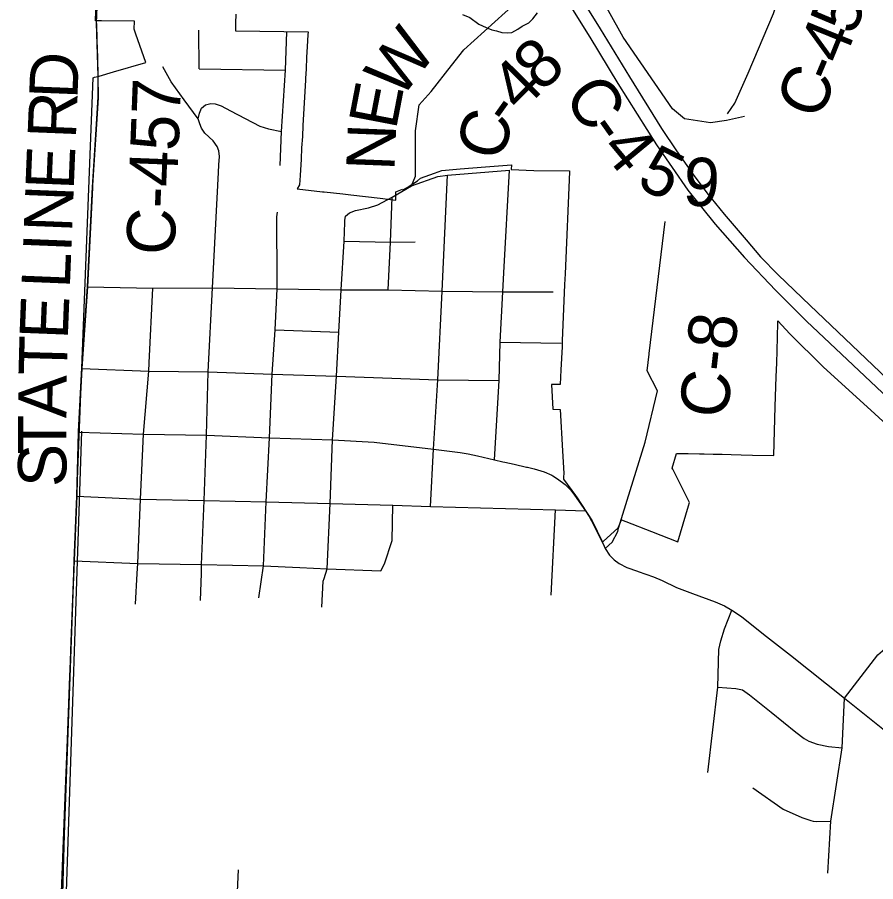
# Model space of a CAD drawing. Extents: x -7.5 to 26.5, y 3.5 to 25.5.
# Drawn here: x -5.276 to -4.268, y 21.705 to 22.72 of the extents above; entities that cross this region are included whole.
import ezdxf

# ---------------------------------------------------------------- set-up
doc = ezdxf.new("R2010")
doc.units = 0
for name, color, linetype in [('GM_X_City_Street', 7, 'Continuous'), ('GM_X_Corporation', 7, 'Continuous'), ('GM_X_County_Road', 7, 'Continuous'), ('GM_X_County_Road_Text', 7, 'Continuous'), ('GM_X_Interstate_Route', 7, 'Continuous'), ('GM_X_Minor_River', 7, 'Continuous'), ('GM_X_Rail_Line', 7, 'Continuous'), ('GM_X_US_Route', 7, 'Continuous')]:
    doc.layers.add(name, color=color, linetype=linetype)

msp = doc.modelspace()

# ---------------------------------------------------------------- linework, layer by layer
at = {"layer": 'GM_X_City_Street'}
for p, q in [((-5.0619, 22.6592), (-5.0626, 22.7046)), ((-5.0619, 22.6592), (-4.9606, 22.6578)), ((-4.7045, 22.4196), (-4.6976, 22.5402)), ((-5.1206, 22.3141), (-5.1166, 22.4018)), ((-5.0513, 22.3034), (-5.0462, 22.4022)), ((-4.9729, 22.3528), (-4.898, 22.3501)), ((-4.7087, 22.3384), (-4.6371, 22.337)), ((-5.0534, 22.2289), (-5.0513, 22.3034)), ((-4.7904, 22.1455), (-4.7869, 22.2126)), ((-4.6488, 22.0413), (-4.6436, 22.1413)), ((-4.992, 22.0379), (-4.9865, 22.0757)), ((-5.1366, 22.0308), (-5.1348, 22.0665)), ((-5.0603, 22.0348), (-5.0594, 22.0667))]:
    msp.add_line(p, q, dxfattribs=at)
for points in [[(-4.9671, 22.5459), (-4.9655, 22.5855), (-4.9606, 22.6578), (-4.959, 22.7027)], [(-5.063, 22.6007), (-5.0795, 22.6227), (-5.0949, 22.644), (-5.1045, 22.6615)], [(-5.0388, 22.5465), (-5.0382, 22.5565), (-5.039, 22.5628), (-5.0408, 22.5682), (-5.0457, 22.5747), (-5.0554, 22.5836), (-5.0593, 22.5895), (-5.0612, 22.5948), (-5.063, 22.6007), (-5.0616, 22.6072), (-5.0591, 22.6129), (-5.0544, 22.6168), (-5.0483, 22.6185), (-5.0432, 22.6183), (-5.0361, 22.6159), (-5.0254, 22.6099), (-4.991, 22.5921), (-4.9807, 22.589), (-4.9655, 22.5855)], [(-5.0462, 22.4022), (-5.0394, 22.5375), (-5.0388, 22.5465)], [(-4.8128, 22.5218), (-4.7817, 22.5329), (-4.7707, 22.5345), (-4.6976, 22.5402)], [(-4.7869, 22.2126), (-4.7817, 22.2939), (-4.7766, 22.3982), (-4.7707, 22.5345)], [(-4.84, 22.3997), (-4.8375, 22.4559), (-4.8356, 22.5086)], [(-4.9705, 22.4101), (-4.9708, 22.4854), (-4.9699, 22.4911)], [(-4.892, 22.4569), (-4.8375, 22.4559), (-4.8086, 22.4563)], [(-4.7153, 22.2), (-4.7099, 22.2932), (-4.7087, 22.3384), (-4.7057, 22.3976), (-4.7045, 22.4196)], [(-5.1932, 22.4031), (-5.1166, 22.4018), (-5.0462, 22.4022), (-4.9704, 22.4011), (-4.8955, 22.3997), (-4.84, 22.3997), (-4.7766, 22.3982), (-4.7057, 22.3976), (-4.6465, 22.3976)], [(-4.9793, 22.2259), (-4.9762, 22.3008), (-4.9729, 22.3528), (-4.9704, 22.4011), (-4.9705, 22.4101)], [(-5.1273, 22.2303), (-5.1211, 22.3044), (-5.1206, 22.3141)], [(-5.1999, 22.3075), (-5.1211, 22.3044), (-5.0513, 22.3034), (-4.9762, 22.3008), (-4.9009, 22.2984), (-4.7817, 22.2939), (-4.7099, 22.2932)], [(-5.1348, 22.0665), (-5.1342, 22.0784), (-5.1307, 22.1541), (-5.1273, 22.2303)], [(-5.0594, 22.0667), (-5.0591, 22.0774), (-5.0563, 22.1522), (-5.0534, 22.2289)], [(-4.9865, 22.0757), (-4.9832, 22.1507), (-4.9793, 22.2259)], [(-4.9152, 22.0609), (-4.9116, 22.0722), (-4.9084, 22.149), (-4.9055, 22.2235)], [(-5.2056, 22.1576), (-5.1307, 22.1541), (-5.0563, 22.1522), (-4.9832, 22.1507), (-4.9084, 22.149), (-4.8347, 22.1469), (-4.7904, 22.1455), (-4.6436, 22.1413), (-4.6084, 22.1403)], [(-4.8489, 22.0697), (-4.8445, 22.0779), (-4.8356, 22.1053), (-4.8347, 22.1469)], [(-5.2087, 22.0816), (-5.1342, 22.0784), (-5.0591, 22.0774), (-4.9865, 22.0757), (-4.9437, 22.0737)], [(-4.9437, 22.0737), (-4.9116, 22.0722), (-4.8489, 22.0697)], [(-4.9179, 22.0271), (-4.9163, 22.0575), (-4.9152, 22.0609)], [(-4.465, 21.8328), (-4.4533, 21.9332), (-4.4519, 21.9773), (-4.4495, 21.9876), (-4.4454, 22.0017), (-4.4369, 22.0237)], [(-4.4533, 21.9332), (-4.4319, 21.9317), (-4.4242, 21.9299), (-4.416, 21.9243), (-4.3907, 21.9037), (-4.3615, 21.8802), (-4.3518, 21.8729), (-4.3462, 21.8699), (-4.3365, 21.8661), (-4.3233, 21.8634), (-4.3071, 21.862)], [(-4.3239, 21.7149), (-4.3206, 21.776), (-4.3071, 21.862), (-4.3045, 21.9204)], [(-4.4121, 21.8148), (-4.3764, 21.79), (-4.3547, 21.7802), (-4.3442, 21.7768), (-4.3411, 21.776), (-4.3371, 21.7754), (-4.3206, 21.776)], [(-5.0161, 21.7187), (-5.0173, 21.6931), (-5.0192, 21.6484), (-5.019, 21.6362), (-5.0182, 21.5986), (-5.0154, 21.581), (-5.0119, 21.5703), (-5.0005, 21.5585), (-4.9717, 21.5382), (-4.9022, 21.4895), (-4.8962, 21.4882), (-4.8863, 21.4894), (-4.8713, 21.4949)]]:
    msp.add_lwpolyline(points, dxfattribs=at)
at = {"layer": 'GM_X_Corporation'}
for points in [[(-5.1194, 24.4), (-5.1615, 23.2384), (-5.1616, 23.2356), (-5.1623, 23.2179), (-5.1829, 22.7129), (-5.1811, 22.6509), (-5.181, 22.6264), (-5.1825, 22.6005), (-5.1876, 22.5202), (-5.1934, 22.4036), (-5.2001, 22.3081), (-5.204, 22.2333), (-5.2058, 22.1581), (-5.2089, 22.0821), (-5.2103, 22.0432), (-5.2204, 21.7606), (-5.2223, 21.6911)], [(-5.1194, 24.4), (-5.1615, 23.2384), (-5.1616, 23.2356), (-5.1623, 23.2179), (-5.1829, 22.7129), (-5.1811, 22.6509), (-5.181, 22.6264), (-5.1825, 22.6005), (-5.1876, 22.5202), (-5.1934, 22.4036), (-5.2001, 22.3081), (-5.204, 22.2333), (-5.2058, 22.1581), (-5.2089, 22.0821), (-5.2103, 22.0432), (-5.2204, 21.7606), (-5.2223, 21.6911)], [(-5.2255, 21.6421), (-5.2193, 21.8036), (-5.2167, 21.8716), (-5.2138, 21.946), (-5.2135, 21.9548), (-5.2132, 21.964), (-5.2127, 21.9756), (-5.2123, 21.987), (-5.1866, 22.6488), (-5.1849, 22.6493), (-5.1794, 22.6508), (-5.1624, 22.6557), (-5.1248, 22.6669), (-5.1364, 22.7), (-5.1385, 22.7059), (-5.1379, 22.7153), (-5.1768, 22.7158), (-5.1839, 22.7158), (-5.1826, 22.7493)], [(-5.0188, 22.7236), (-5.0192, 22.7128), (-5.0194, 22.7082), (-5.0195, 22.704), (-4.9342, 22.7029), (-4.9344, 22.699), (-4.9351, 22.6856), (-4.9359, 22.6724), (-4.9366, 22.6591), (-4.9372, 22.6478), (-4.9373, 22.6459), (-4.938, 22.6327), (-4.9384, 22.626), (-4.9388, 22.6194), (-4.9395, 22.6062), (-4.9402, 22.5929), (-4.9409, 22.5797), (-4.9417, 22.5665), (-4.9424, 22.5532), (-4.9435, 22.5339), (-4.9441, 22.523), (-4.947, 22.5184), (-4.9173, 22.515), (-4.9151, 22.5148), (-4.8933, 22.5123), (-4.8839, 22.5112), (-4.8495, 22.5073), (-4.8405, 22.5063), (-4.8313, 22.5052), (-4.8312, 22.5082), (-4.8311, 22.512), (-4.831, 22.5148), (-4.8234, 22.5179), (-4.8229, 22.517), (-4.8179, 22.5201), (-4.8057, 22.5276), (-4.8021, 22.5307), (-4.7857, 22.5367), (-4.7771, 22.5399), (-4.7558, 22.5417), (-4.7259, 22.5441), (-4.6953, 22.5466), (-4.6956, 22.541), (-4.6691, 22.5399), (-4.6273, 22.5394), (-4.6273, 22.5383), (-4.6325, 22.4186), (-4.633, 22.406), (-4.6358, 22.34), (-4.6361, 22.333), (-4.6373, 22.306), (-4.6383, 22.2886), (-4.6483, 22.2887), (-4.6467, 22.2597), (-4.6381, 22.2594), (-4.6355, 22.2107), (-4.634, 22.184), (-4.6343, 22.18), (-4.6345, 22.1774), (-4.6202, 22.1583), (-4.6191, 22.1568), (-4.6008, 22.1285), (-4.5885, 22.1034), (-4.5877, 22.1041), (-4.57, 22.1201), (-4.5663, 22.1297), (-4.5613, 22.1277), (-4.531, 22.1159), (-4.5001, 22.1037), (-4.4877, 22.146), (-4.4865, 22.1501), (-4.4922, 22.1616), (-4.5059, 22.189), (-4.5066, 22.1904), (-4.5015, 22.2076), (-4.4981, 22.2076), (-4.4892, 22.2074), (-4.4879, 22.2074), (-4.4745, 22.2071), (-4.4693, 22.207), (-4.4587, 22.2068), (-4.4481, 22.2066), (-4.4375, 22.2064), (-4.4258, 22.2061), (-4.4125, 22.2058), (-4.3876, 22.2053), (-4.3857, 22.2627), (-4.3846, 22.2976), (-4.3841, 22.3139), (-4.3837, 22.3281), (-4.3829, 22.3612), (-4.3828, 22.3632), (-4.3687, 22.3482), (-4.3295, 22.3092), (-4.269, 22.2541), (-4.2451, 22.2323)]]:
    msp.add_lwpolyline(points, dxfattribs=at)
at = {"layer": 'GM_X_County_Road'}
for p, q in [((-5.1826, 22.7124), (-5.1821, 22.6924)), ((-5.1821, 22.6924), (-5.1815, 22.6724)), ((-4.5336, 22.3251), (-4.5151, 22.4799)), ((-4.9055, 22.2235), (-4.9009, 22.2984)), ((-5.201, 22.2851), (-5.2037, 22.2328))]:
    msp.add_line(p, q, dxfattribs=at)
for points in [[(-4.442, 22.6063), (-4.4334, 22.6189), (-4.4176, 22.654), (-4.3877, 22.7241), (-4.3725, 22.7693), (-4.3633, 22.8101), (-4.3488, 22.8633), (-4.342, 22.8894), (-4.3327, 22.9169), (-4.3053, 22.9874), (-4.2936, 23.0185), (-4.2858, 23.0352), (-4.2614, 23.0699), (-4.2366, 23.1021), (-4.2215, 23.121), (-4.2094, 23.1319), (-4.1964, 23.1423), (-4.1751, 23.1597), (-4.1572, 23.1752), (-4.1429, 23.1922), (-4.122, 23.2193), (-4.1074, 23.2375), (-4.0945, 23.253), (-4.0327, 23.3282)], [(-4.4616, 22.5957), (-4.4922, 22.6005), (-4.5062, 22.6123), (-4.5642, 22.6963), (-4.6199, 22.7966)], [(-4.8128, 22.5218), (-4.808, 22.5334), (-4.8079, 22.5446), (-4.8081, 22.5865), (-4.8037, 22.6168), (-4.7898, 22.6327), (-4.7657, 22.663), (-4.7514, 22.6816), (-4.7027, 22.7255), (-4.6618, 22.7623), (-4.6498, 22.7714), (-4.6407, 22.7791)], [(-5.1815, 22.6724), (-5.1809, 22.6503), (-5.1807, 22.6258), (-5.1822, 22.6), (-5.1871, 22.5227)], [(-4.422, 22.6033), (-4.4431, 22.5986), (-4.4616, 22.5957)], [(-5.1871, 22.5227), (-5.1873, 22.5196), (-5.1932, 22.4031), (-5.1999, 22.3075), (-5.201, 22.2851)], [(-4.891, 22.479), (-4.8909, 22.4812), (-4.8901, 22.4864), (-4.8854, 22.4903), (-4.8787, 22.4929), (-4.8632, 22.4962), (-4.8524, 22.4997), (-4.8356, 22.5086), (-4.8128, 22.5218)], [(-4.9009, 22.2984), (-4.898, 22.3501), (-4.8955, 22.3997), (-4.892, 22.4569), (-4.891, 22.479)], [(-4.5696, 22.1197), (-4.5562, 22.1643), (-4.5384, 22.221), (-4.5239, 22.2811), (-4.536, 22.3046), (-4.5337, 22.3241), (-4.5336, 22.3251)], [(-5.2104, 22.0317), (-5.21, 22.0427), (-5.2087, 22.0816), (-5.2056, 22.1576), (-5.2037, 22.2328)], [(-5.2037, 22.2328), (-5.1273, 22.2303), (-5.0534, 22.2289), (-4.9793, 22.2259), (-4.9055, 22.2235)], [(-4.9055, 22.2235), (-4.8565, 22.2208), (-4.7869, 22.2126)], [(-4.7869, 22.2126), (-4.7558, 22.2088), (-4.7464, 22.2073), (-4.7353, 22.2047)], [(-4.7353, 22.2047), (-4.7153, 22.2), (-4.7054, 22.1979)], [(-4.7054, 22.1979), (-4.7034, 22.1975), (-4.6922, 22.195), (-4.6776, 22.1916), (-4.6766, 22.1914)], [(-4.6766, 22.1914), (-4.6687, 22.1896), (-4.6572, 22.1861), (-4.6481, 22.1822), (-4.647, 22.1815), (-4.6414, 22.1779), (-4.6322, 22.1711), (-4.6258, 22.1645), (-4.6213, 22.1587), (-4.6084, 22.1403), (-4.6043, 22.1334), (-4.5987, 22.1234), (-4.5867, 22.0988), (-4.5854, 22.0961)], [(-4.5854, 22.0961), (-4.5772, 22.1035), (-4.5707, 22.116), (-4.5696, 22.1197)], [(-4.5854, 22.0961), (-4.5802, 22.0882), (-4.5748, 22.0828), (-4.569, 22.0785), (-4.5599, 22.0737), (-4.5474, 22.0693), (-4.5465, 22.0689)], [(-4.3045, 21.9204), (-4.2653, 21.9711), (-4.2599, 21.9759), (-4.2427, 21.9915), (-4.2156, 22.0097), (-4.1146, 22.0653), (-4.0805, 22.0844)], [(-4.5465, 22.0689), (-4.5288, 22.0627), (-4.5185, 22.0584)], [(-4.5185, 22.0584), (-4.5015, 22.0503), (-4.4831, 22.0431), (-4.4565, 22.0332), (-4.4454, 22.0285), (-4.4369, 22.0237), (-4.4254, 22.016), (-4.3996, 21.9956)], [(-5.2221, 21.6906), (-5.2201, 21.7601), (-5.2104, 22.0317)], [(-4.3996, 21.9956), (-4.3679, 21.9706), (-4.3045, 21.9204)], [(-4.3045, 21.9204), (-4.2849, 21.9046), (-4.1655, 21.8092), (-4.1097, 21.7644)]]:
    msp.add_lwpolyline(points, dxfattribs=at)
at = {"layer": 'GM_X_Interstate_Route'}
for points in [[(-5.162, 23.2174), (-5.0899, 23.1819), (-5.0197, 23.1473), (-4.9468, 23.11), (-4.9056, 23.0854), (-4.8753, 23.0652), (-4.8477, 23.0451), (-4.824, 23.0227), (-4.803, 22.9999), (-4.7793, 22.9735), (-4.7534, 22.9389), (-4.7236, 22.8924), (-4.6911, 22.8389), (-4.6498, 22.7714), (-4.6034, 22.6963), (-4.5705, 22.6419), (-4.5253, 22.57), (-4.4885, 22.5169), (-4.4564, 22.477), (-4.4218, 22.4379), (-4.3854, 22.3993), (-4.349, 22.3629), (-4.1846, 22.2079)], [(-4.6378, 22.7814), (-4.5913, 22.7062), (-4.5569, 22.65), (-4.5194, 22.5893), (-4.5016, 22.563), (-4.4821, 22.5351), (-4.4659, 22.5136), (-4.4459, 22.4888), (-4.4198, 22.4583), (-4.4031, 22.4387), (-4.3823, 22.4175), (-4.3448, 22.3814), (-4.1567, 22.202)]]:
    msp.add_lwpolyline(points, dxfattribs=at)
at = {"layer": 'GM_X_Minor_River'}
msp.add_lwpolyline([(-4.7528, 22.7232), (-4.7441, 22.7196), (-4.7337, 22.7117), (-4.725, 22.708), (-4.7183, 22.7051), (-4.713, 22.7038), (-4.7069, 22.7021), (-4.6997, 22.7015), (-4.6948, 22.7021), (-4.6878, 22.7057), (-4.6827, 22.7093), (-4.675, 22.7133), (-4.6703, 22.7181), (-4.6648, 22.7251)], dxfattribs=at)
at = {"layer": 'GM_X_Rail_Line'}
msp.add_line((-5.2239, 21.5005), (-5.1999, 22.2339), dxfattribs=at)
at = {"layer": 'GM_X_US_Route'}
msp.add_lwpolyline([(-5.162, 23.2174), (-5.0899, 23.1819), (-5.0197, 23.1473), (-4.9468, 23.11), (-4.9056, 23.0854), (-4.8753, 23.0652), (-4.8477, 23.0451), (-4.824, 23.0227), (-4.803, 22.9999), (-4.7793, 22.9735), (-4.7534, 22.9389), (-4.7236, 22.8924), (-4.6911, 22.8389), (-4.6498, 22.7714), (-4.6034, 22.6963), (-4.5705, 22.6419), (-4.5253, 22.57), (-4.4885, 22.5169), (-4.4564, 22.477), (-4.4218, 22.4379), (-4.3854, 22.3993), (-4.349, 22.3629), (-4.1846, 22.2079)], dxfattribs=at)

# ---------------------------------------------------------------- texts
at = {"layer": 'GM_X_County_Road_Text'}
for s, height, rotation, p in [('5', 0.0568, 70.5098, (-4.2928, 22.6975)), ('W', 0.0568, 52.4291, (-4.8259, 22.6221)), ('4', 0.0568, 67.9287, (-4.307, 22.6625)), ('8', 0.0568, 42.7678, (-4.6604, 22.6308)), ('D', 0.0568, 87.6994, (-5.205, 22.6232)), ('4', 0.0568, 45.0924, (-4.6847, 22.6064)), ('-', 0.0568, 67.2092, (-4.3163, 22.6403)), ('C', 0.0568, 67.0176, (-4.3346, 22.5971)), ('C', 0.0568, 304.2541, (-4.6355, 22.6269)), ('C-457', 0.05682, 87.7972, (-5.091, 22.4399)), ('E', 0.0568, 79.1376, (-4.8311, 22.5867)), ('R', 0.0568, 87.6993, (-5.2068, 22.5765)), ('-', 0.0568, 54.469, (-4.6967, 22.5893)), ('C', 0.0568, 74.7269, (-4.7067, 22.549)), ('-', 0.0568, 305.1995, (-4.6086, 22.5875)), ('N', 0.0568, 87.6983, (-4.8328, 22.5389)), ('4', 0.0568, 309.6436, (-4.5923, 22.5646)), ('5', 0.0568, 332.9658, (-4.5504, 22.5219)), ('E', 0.0568, 87.6994, (-5.2093, 22.5166)), ('9', 0.0568, 356.3224, (-4.495, 22.4994)), ('N', 0.0568, 87.6994, (-5.2113, 22.4666)), ('I', 0.0568, 87.699, (-5.2122, 22.4433)), ('L', 0.0568, 87.6994, (-5.2139, 22.4008)), ('E', 0.0568, 87.742, (-5.2163, 22.3409)), ('C-8', 0.05682, 83.5598, (-4.4424, 22.2475)), ('T', 0.0568, 88.4413, (-5.2174, 22.2986)), ('A', 0.0568, 89.5227, (-5.2178, 22.2489)), ('T', 0.0568, 89.996, (-5.2178, 22.2065)), ('S', 0.0568, 90, (-5.2178, 22.1682))]:
    msp.add_text(s, height=height, rotation=rotation, dxfattribs=at).set_placement(p)

doc.saveas('drawing.dxf')
